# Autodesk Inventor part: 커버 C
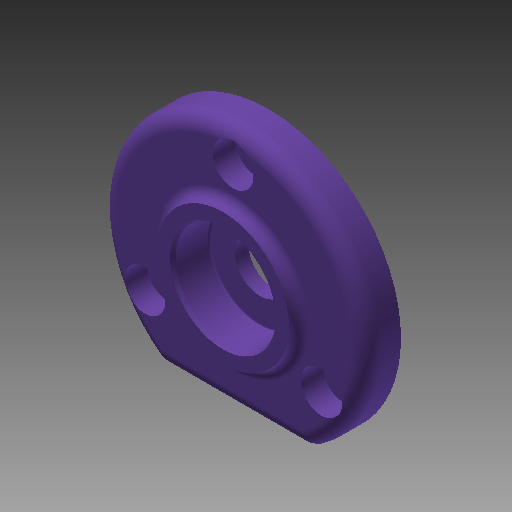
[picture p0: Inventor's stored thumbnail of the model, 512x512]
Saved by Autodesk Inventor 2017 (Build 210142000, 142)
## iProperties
Created: 2020-04
Part Number: 커버 C
Material: 알루미늄 6061
Document SubType Name: Modeling
Designer: mduedu
Density: 2.71 g/cm^3
Appearance: 보라색
Mass: 35.2365 g
Surface Area: 62.3737 cm^2
Volume: 13.0024 cm^3
Author: mduedu
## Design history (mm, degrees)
sketch "스케치1"
  geometry: C1 r 26 at (0, 0); 1 further point
  constraints: 1 centre point, 1 coincident
  dimensions: "d0" = 52 diameter of C1
extrude "돌출1" new body sketch "스케치1" distance "d1" = 7; taper "d2" = 0 deg
sketch "스케치2"
  geometry: L1 (-14.62, -21.5)-(14.62, -21.5); A1 r 26 centre (0, 0) between (-14.62, -21.5) and (14.62, -21.5) reference; 1 further point
  constraints: 2 end point, 2 point on circle, 1 horizontal
  dimensions: "d3" = 21.5 distance from line of L1 point (0, 0)
extrude "돌출2" cut sketch "스케치2" stored distance "d4" = 7; taper "d5" = 0 deg
sketch "스케치6"
  geometry: C1 r 13 at (0, 0); 1 further point
  constraints: 1 centre point, 1 coincident
  dimensions: "d29" = 26 diameter of C1
extrude "돌출5" join sketch "스케치6" distance "d30" = 2; taper "d31" = 0 deg
fillet "모깎기1" dims "d6" = 3
fillet "모깎기2" dims "d7" = 3
fillet "모깎기4" dims "d33" = 2
sketch "스케치3" dims "d8" = 40
  geometry: 3 further points
  constraints: 2 vertical alignment, 1 coincident, 2 other
hole "구멍1" sketch "스케치3" at (0, 20) diameter "d9" = 4.5; stored, may be unused: countersink angle "d13" = 90 deg, drill point angle "d15" = 118 deg; dims "d10" = 6, "d11" = 8, "d12" = 4.4, "d14" = 8
sketch "스케치4"
  geometry: C1 r 14 at (0, 0); 1 further point
  constraints: 1 centre point, 1 coincident
  dimensions: "d19" = 28 diameter of C1
extrude "돌출3" join sketch "스케치4" distance "d20" = 4; taper "d21" = 0 deg
sketch "스케치5"
  geometry: C1 r 12 at (0, 0); 1 further point
  constraints: 1 centre point, 1 coincident
  dimensions: "d22" = 24 diameter of C1
extrude "돌출4" cut sketch "스케치5" distance "d23" = 3; taper "d24" = 0 deg
fillet "모깎기3" dims "d25" = 3
chamfer "모따기1" distance "d26" = 0.5; stored, may be unused: second distance "d27" = 2, angle "d28" = 45 deg
sketch "스케치7"
  geometry: 2 further points
  constraints: 1 coincident
hole "구멍2" sketch "스케치7" at (0, 0) diameter "d34" = 10; stored, may be unused: countersink angle "d38" = 90 deg, drill point angle "d40" = 118 deg; dims "d35" = 6, "d36" = 20, "d37" = 7.3, "d39" = 8
fillet "모깎기5" dims "d41" = 0.3
chamfer "모따기2" distance "d42" = 0.7; stored, may be unused: second distance "d43" = 2, angle "d44" = 30 deg
node "솔리드1"
pattern_circular "원형 패턴1" dims angle "d17" = 360 deg
node "투영된 루프1"
